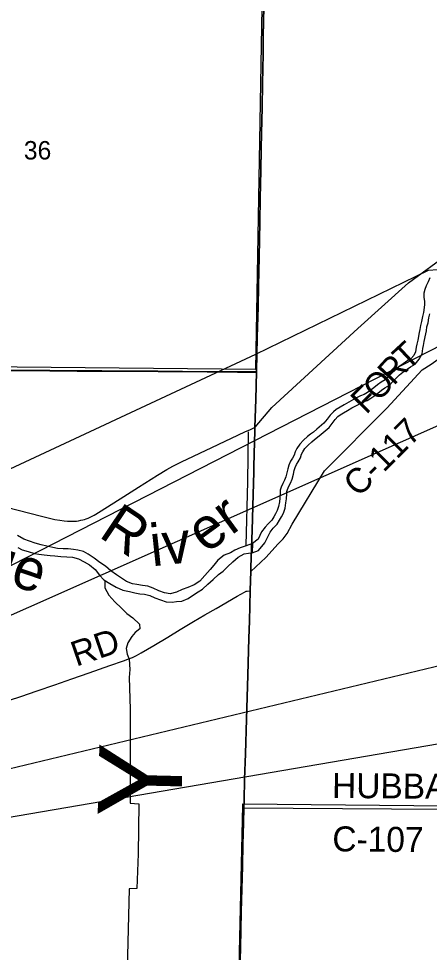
# Model space of a CAD drawing. Extents: x -8.3 to 42.1, y 0 to 22.
# Drawn here: x 7.372 to 8.304, y 16.982 to 19.103 of the extents above; entities that cross this region are included whole.
import ezdxf

# ---------------------------------------------------------------- set-up
doc = ezdxf.new("R2010")
doc.units = 0
for name, color, linetype in [('GM_X_County_Road', 7, 'Continuous'), ('GM_X_County_Road_Text', 7, 'Continuous'), ('GM_X_County_Text', 7, 'Continuous'), ('GM_X_Major_River', 7, 'Continuous'), ('GM_X_Major_River_Text', 7, 'Continuous'), ('GM_X_Minor_River', 7, 'Continuous'), ('GM_X_Rail_Line', 7, 'Continuous'), ('GM_X_Section', 7, 'Continuous'), ('GM_X_Section_Text', 7, 'Continuous'), ('GM_X_State_Route', 7, 'Continuous'), ('GM_X_Township_Road', 7, 'Continuous'), ('GM_X_Township_Road_Text', 7, 'Continuous'), ('GM_X_US_Route', 7, 'Continuous'), ('SH_Cut_Line', 7, 'Continuous'), ('SH_Text', 7, 'Continuous')]:
    doc.layers.add(name, color=color, linetype=linetype)

msp = doc.modelspace()

# ---------------------------------------------------------------- linework, layer by layer
at = {"layer": 'GM_X_County_Road'}
for points in [[(7.8987, 17.8473), (7.933, 17.8784), (7.9603, 17.9099), (7.9717, 17.9213), (7.9812, 17.9331), (7.9926, 17.9548), (8.0656, 18.0756), (8.2076, 18.2177), (8.2873, 18.3051), (8.3078, 18.3181), (8.5197, 18.4682), (8.7205, 18.6119), (8.7539, 18.6347), (8.8458, 18.7042), (8.9, 18.7436)], [(6.9106, 18.3053), (6.945, 18.3048), (6.9948, 18.3048), (7.029, 18.3045), (7.0663, 18.3044), (7.0911, 18.3043), (7.144, 18.3041), (7.2186, 18.3036), (7.2559, 18.3034), (7.3398, 18.3031), (7.4424, 18.3029), (7.5045, 18.3023), (7.5605, 18.3019), (7.6413, 18.3016), (7.6879, 18.3013), (7.7998, 18.3003), (7.8682, 18.3), (7.9024, 18.2999), (7.9119, 18.2999)], [(7.8831, 17.31), (8.8875, 17.3037), (8.9, 17.3036)]]:
    msp.add_lwpolyline(points, dxfattribs=at)
at = {"layer": 'GM_X_Major_River'}
msp.add_line((7.9027, 17.9106), (7.9019, 17.889), dxfattribs=at)
for points in [[(8.3052, 18.5138), (8.3014, 18.5047), (8.2969, 18.4956), (8.2935, 18.4872), (8.2913, 18.4792), (8.2913, 18.4697), (8.2925, 18.4599), (8.2925, 18.4534), (8.2921, 18.4466), (8.2903, 18.4352), (8.2881, 18.426), (8.2862, 18.415), (8.2836, 18.4059), (8.2821, 18.3964), (8.2806, 18.3899), (8.2773, 18.3721), (8.2754, 18.3633), (8.2739, 18.3565), (8.2724, 18.3462), (8.2683, 18.3379), (8.2615, 18.3299), (8.2524, 18.3249), (8.2441, 18.3188), (8.2342, 18.3115), (8.2259, 18.3046), (8.2176, 18.2966), (8.21, 18.289), (8.2036, 18.2821), (8.1945, 18.2767), (8.1862, 18.2706), (8.1779, 18.2641), (8.1714, 18.2592), (8.1631, 18.2538), (8.1555, 18.2492), (8.1476, 18.2458), (8.1411, 18.2427), (8.1317, 18.2377), (8.1207, 18.2319), (8.1101, 18.2258), (8.1014, 18.2205), (8.0923, 18.2151), (8.0859, 18.2097), (8.0787, 18.2021), (8.0715, 18.1926), (8.0643, 18.1838)], [(8.0761, 18.1742), (8.0834, 18.1832), (8.0903, 18.1923), (8.0963, 18.1987), (8.1011, 18.2027), (8.1092, 18.2075), (8.1179, 18.2128), (8.128, 18.2187), (8.1387, 18.2243), (8.1479, 18.2291), (8.1539, 18.232), (8.1625, 18.2357), (8.1711, 18.2409), (8.1802, 18.2468), (8.1872, 18.2522), (8.1953, 18.2585), (8.2029, 18.2641), (8.2132, 18.2702), (8.221, 18.2785), (8.2282, 18.2858), (8.236, 18.2933), (8.2436, 18.2995), (8.2531, 18.3066), (8.2606, 18.3121), (8.2712, 18.3179), (8.281, 18.3295), (8.2871, 18.3417), (8.2888, 18.3538), (8.2902, 18.3601), (8.2921, 18.3691), (8.2954, 18.3868), (8.297, 18.3935), (8.2984, 18.4026), (8.301, 18.4117), (8.3029, 18.423), (8.3052, 18.4321)], [(7.9019, 17.889), (7.9163, 17.8944), (7.9303, 17.9124), (7.9428, 17.9361), (7.9493, 17.9451), (7.958, 17.9544), (7.964, 17.9636), (7.9681, 17.9711), (7.9725, 17.9796), (7.9762, 17.9909), (7.9783, 18.0029), (7.9795, 18.0117), (7.9803, 18.0234), (7.9803, 18.0288), (7.9819, 18.0332), (7.9849, 18.0407), (7.9886, 18.0477), (7.9927, 18.057), (7.9953, 18.0681), (7.997, 18.0765), (7.9993, 18.083), (8.002, 18.0903), (8.0057, 18.096), (8.0111, 18.1048), (8.0135, 18.1132), (8.0163, 18.119), (8.0213, 18.1264), (8.0288, 18.1341), (8.0367, 18.1417), (8.0432, 18.1465), (8.0501, 18.1518), (8.0583, 18.1589), (8.0761, 18.1742)], [(8.0643, 18.1838), (8.0485, 18.1704), (8.0405, 18.1636), (8.0341, 18.1586), (8.0269, 18.1533), (8.0182, 18.1449), (8.0095, 18.1361), (8.0031, 18.1266), (7.9993, 18.1186), (7.9971, 18.111), (7.9929, 18.1041), (7.9884, 18.0972), (7.985, 18.0881), (7.9824, 18.0805), (7.9805, 18.0714), (7.9783, 18.0619), (7.9749, 18.0543), (7.9711, 18.047), (7.9678, 18.0387), (7.9651, 18.0315), (7.9652, 18.0239), (7.9644, 18.0132), (7.9633, 18.0052), (7.9615, 17.9946), (7.9585, 17.9855), (7.9547, 17.9783), (7.9509, 17.9714), (7.946, 17.9638), (7.9381, 17.9554), (7.9309, 17.9474), (7.9227, 17.9368), (7.915, 17.9204), (7.9027, 17.9106)], [(7.9027, 17.9106), (7.8878, 17.9054), (7.8744, 17.9008), (7.8625, 17.8954), (7.8522, 17.8896), (7.838, 17.8838), (7.8239, 17.8724), (7.8144, 17.8613), (7.8065, 17.8512), (7.7945, 17.8382), (7.7832, 17.8252), (7.7697, 17.8168), (7.7555, 17.8103), (7.7426, 17.8061), (7.7295, 17.8003), (7.7158, 17.7965), (7.703, 17.7983), (7.6895, 17.8032), (7.6771, 17.8092), (7.6647, 17.8133), (7.6527, 17.8155), (7.6398, 17.8173), (7.63, 17.8187), (7.6161, 17.8243), (7.605, 17.8322), (7.5938, 17.8397), (7.5811, 17.8483), (7.5685, 17.8589), (7.5559, 17.8675), (7.5432, 17.8769), (7.5294, 17.8864), (7.519, 17.8923), (7.5062, 17.8953), (7.496, 17.8971), (7.4839, 17.8981), (7.4726, 17.8988), (7.4597, 17.8991), (7.4492, 17.9016), (7.4356, 17.9042), (7.4224, 17.9076), (7.4093, 17.9113), (7.3961, 17.9158), (7.3833, 17.9203), (7.3692, 17.929)], [(7.3696, 17.9017), (7.3797, 17.8965), (7.3929, 17.8924), (7.4075, 17.8878), (7.4173, 17.8865), (7.4294, 17.885), (7.4434, 17.8835), (7.4536, 17.8822), (7.4672, 17.8811), (7.4808, 17.8804), (7.494, 17.8793), (7.5076, 17.8755), (7.5203, 17.8688), (7.5322, 17.862), (7.5452, 17.8515), (7.5548, 17.8387), (7.5646, 17.8283), (7.5782, 17.8199), (7.5927, 17.8112), (7.6081, 17.8044), (7.6231, 17.8014), (7.6356, 17.7984), (7.6465, 17.7966), (7.6575, 17.7956), (7.6695, 17.7923), (7.6804, 17.7871), (7.7062, 17.7777), (7.7199, 17.7774), (7.7298, 17.7791), (7.7423, 17.7799), (7.756, 17.7853), (7.7661, 17.7926)], [(7.7661, 17.7926), (7.7792, 17.801), (7.7888, 17.8072), (7.8008, 17.8179), (7.8132, 17.829), (7.8252, 17.8401), (7.8356, 17.8478), (7.8457, 17.8575), (7.8581, 17.8689), (7.8701, 17.8793), (7.8832, 17.8869), (7.893, 17.8886), (7.9019, 17.889)]]:
    msp.add_lwpolyline(points, dxfattribs=at)
at = {"layer": 'GM_X_Minor_River'}
for points in [[(7.8882, 17.9058), (7.8914, 18.051), (7.8931, 18.1641)], [(7.5669, 17.8244), (7.5669, 17.81), (7.5764, 17.7934), (7.59, 17.7779), (7.6052, 17.7639), (7.617, 17.7514), (7.6311, 17.7416), (7.6459, 17.7272), (7.6468, 17.7166), (7.6364, 17.7088), (7.6282, 17.6995), (7.6191, 17.685), (7.6158, 17.6721), (7.6181, 17.6592), (7.6224, 17.6477), (7.624, 17.6241), (7.6221, 17.6063), (7.6245, 17.5342), (7.6245, 17.3979), (7.6248, 17.3205), (7.6445, 17.3196), (7.6428, 17.2054), (7.6401, 17.1269), (7.6223, 17.1266), (7.6193, 17.0045), (7.6167, 16.8842)]]:
    msp.add_lwpolyline(points, dxfattribs=at)
at = {"layer": 'GM_X_Rail_Line'}
for points in [[(7.9103, 18.3409), (8.3022, 18.5316), (8.3223, 18.533), (8.5169, 18.6965), (8.5964, 18.7584), (8.9, 19.0594)], [(5.9044, 17.3082), (6.0693, 17.3942), (6.218, 17.4628), (6.6389, 17.7213), (6.9437, 17.9671), (7.085, 17.9703), (7.2495, 18.0325), (7.9103, 18.3409)]]:
    msp.add_lwpolyline(points, dxfattribs=at)
at = {"layer": 'GM_X_Section'}
for points in [[(7.9268, 19.313), (7.9258, 19.2592), (7.9095, 18.3054), (6.9034, 18.3155), (6.9241, 19.3275)], [(7.8808, 17.3192), (8.8895, 17.3091), (8.8613, 16.3047), (7.8576, 16.3068), (7.8577, 16.3121), (7.8807, 17.3166)]]:
    msp.add_lwpolyline(points, close=True, dxfattribs=at)
at = {"layer": 'GM_X_State_Route'}
for points in [[(7.9083, 18.1745), (7.9462, 18.2196), (8.1416, 18.3992), (8.2566, 18.5029), (8.4426, 18.6386), (8.5067, 18.6856), (8.6077, 18.7682), (8.7266, 18.8854), (8.8749, 19.0334), (8.9, 19.058)], [(7.3437, 17.9933), (7.4238, 17.9728), (7.4449, 17.9674), (7.454, 17.9653), (7.465, 17.9632), (7.475, 17.9618), (7.4824, 17.9612), (7.49, 17.961), (7.4975, 17.9612), (7.5026, 17.9616), (7.5078, 17.9623), (7.5124, 17.9632), (7.5171, 17.9642), (7.5211, 17.9654), (7.5252, 17.9668), (7.5291, 17.9683), (7.5323, 17.9698), (7.5351, 17.9711), (7.5383, 17.9727), (7.5428, 17.975), (7.547, 17.9774), (7.5527, 17.9807), (7.6023, 18.0117), (7.6437, 18.0385), (7.6869, 18.0657), (7.7082, 18.0786), (7.7216, 18.0863), (7.7307, 18.0911), (7.7411, 18.0961), (7.8101, 18.1289), (7.8851, 18.1638), (7.8978, 18.1697), (7.9083, 18.1745)]]:
    msp.add_lwpolyline(points, dxfattribs=at)
at = {"layer": 'GM_X_Township_Road'}
for points in [[(7.3396, 18.3036), (7.4421, 18.3034), (7.5043, 18.3029), (7.5602, 18.3025), (7.6411, 18.3021), (7.6877, 18.3019), (7.7996, 18.3008), (7.868, 18.3005), (7.9022, 18.3005), (7.9117, 18.3005), (7.9117, 18.3027), (7.9133, 18.3789), (7.9149, 18.4473), (7.9158, 18.4955), (7.9172, 18.5607), (7.9189, 18.6415), (7.9199, 18.6944), (7.9216, 18.7581), (7.9223, 18.8078), (7.923, 18.842), (7.924, 18.9011), (7.925, 18.9555), (7.9262, 19.0223), (7.9263, 19.0379), (7.9267, 19.0643), (7.9276, 19.0953), (7.928, 19.1295)], [(7.928, 19.1295), (7.9276, 19.0953), (7.9267, 19.0643), (7.9263, 19.0379), (7.9262, 19.0223), (7.925, 18.9555), (7.924, 18.9011), (7.923, 18.842), (7.9223, 18.8078), (7.9216, 18.7581), (7.9199, 18.6944), (7.9189, 18.6415), (7.9172, 18.5607), (7.9158, 18.4955), (7.9149, 18.4473), (7.9133, 18.3789), (7.9117, 18.3027), (7.9117, 18.3005), (7.91, 18.2375), (7.908, 18.1751), (7.9078, 18.166), (7.9062, 18.1147), (7.9062, 18.1101), (7.9056, 18.0883), (7.9053, 18.0728), (7.9036, 18.0215), (7.9013, 17.9407), (7.8988, 17.8568), (7.8985, 17.8479), (7.8971, 17.804), (7.8971, 17.8036), (7.8952, 17.7341), (7.8942, 17.6952), (7.8916, 17.6113), (7.8886, 17.5119), (7.8863, 17.4327), (7.8845, 17.3752), (7.8833, 17.327), (7.8829, 17.3106), (7.882, 17.2757), (7.8808, 17.2276), (7.8795, 17.1778), (7.8768, 17.0738), (7.8758, 17.0333), (7.8748, 16.993), (7.8741, 16.965)], [(7.8741, 16.965), (7.8748, 16.993), (7.8758, 17.0333), (7.8768, 17.0738), (7.8795, 17.1778), (7.8808, 17.2276), (7.882, 17.2757), (7.8829, 17.3106), (7.8833, 17.327), (7.8845, 17.3752), (7.8863, 17.4327), (7.8886, 17.5119), (7.8916, 17.6113), (7.8942, 17.6952), (7.8952, 17.7341), (7.8971, 17.8036), (7.8971, 17.804), (7.8985, 17.8479), (7.8988, 17.8568), (7.9013, 17.9407), (7.9036, 18.0215), (7.9053, 18.0728), (7.9056, 18.0883), (7.9062, 18.1101), (7.9062, 18.1147), (7.9078, 18.166), (7.908, 18.1751), (7.91, 18.2375), (7.9117, 18.3005), (7.9022, 18.3005), (7.868, 18.3005), (7.7996, 18.3008), (7.6877, 18.3019), (7.6411, 18.3021), (7.5602, 18.3025), (7.5043, 18.3029), (7.4421, 18.3034), (7.3396, 18.3036)], [(7.3509, 17.5544), (7.3768, 17.5632), (7.4138, 17.5759), (7.4538, 17.5898), (7.492, 17.603), (7.5319, 17.6169), (7.5789, 17.6332), (7.6095, 17.6438), (7.6194, 17.6475), (7.6298, 17.6519), (7.6388, 17.6562), (7.6497, 17.662), (7.6782, 17.6787), (7.7101, 17.6982), (7.7383, 17.7153), (7.7686, 17.7336), (7.7938, 17.7483), (7.8196, 17.7633), (7.8675, 17.7911), (7.8841, 17.8004), (7.8857, 17.8011), (7.8868, 17.8016), (7.8881, 17.802), (7.8892, 17.8022), (7.8906, 17.8024), (7.8973, 17.8031)]]:
    msp.add_lwpolyline(points, dxfattribs=at)
at = {"layer": 'GM_X_US_Route'}
for points in [[(7.9119, 18.2999), (7.912, 18.3022), (7.9135, 18.3783), (7.9151, 18.4467), (7.916, 18.4949), (7.9174, 18.5602), (7.9191, 18.641), (7.9201, 18.6938), (7.9218, 18.7575), (7.9226, 18.8073), (7.9232, 18.8415), (7.9242, 18.9005), (7.9252, 18.9549), (7.9264, 19.0218), (7.9265, 19.0373), (7.927, 19.0637), (7.9278, 19.0948), (7.9282, 19.129)], [(7.8743, 16.9644), (7.875, 16.9924), (7.876, 17.0328), (7.877, 17.0732), (7.8797, 17.1773), (7.881, 17.227), (7.8822, 17.2752), (7.8831, 17.31), (7.8835, 17.3265), (7.8847, 17.3746), (7.8865, 17.4321), (7.8888, 17.5113), (7.8918, 17.6108), (7.8944, 17.6947), (7.8954, 17.7335), (7.8973, 17.8031), (7.8987, 17.8473), (7.899, 17.8562), (7.9015, 17.9401), (7.9039, 18.0209), (7.9056, 18.0722), (7.9058, 18.0878), (7.9064, 18.1095), (7.9064, 18.1142), (7.908, 18.1654), (7.9083, 18.1745), (7.9102, 18.2369), (7.9119, 18.2999)]]:
    msp.add_lwpolyline(points, dxfattribs=at)
at = {"layer": 'SH_Cut_Line'}
for points in [[(7.8741, 16.965), (7.8748, 16.993), (7.8758, 17.0333), (7.8768, 17.0738), (7.8795, 17.1778), (7.8808, 17.2276), (7.882, 17.2757), (7.8829, 17.3106), (7.8833, 17.327), (7.8845, 17.3752), (7.8863, 17.4327), (7.8886, 17.5119), (7.8916, 17.6113), (7.8942, 17.6952), (7.8952, 17.7341), (7.8971, 17.8036), (7.8971, 17.804), (7.8985, 17.8479), (7.8988, 17.8568), (7.9013, 17.9407), (7.9036, 18.0215), (7.9053, 18.0728), (7.9056, 18.0883), (7.9062, 18.1101), (7.9062, 18.1147), (7.9078, 18.166), (7.908, 18.1751), (7.91, 18.2375), (7.9117, 18.3005), (7.9117, 18.3027), (7.9133, 18.3789), (7.9149, 18.4473), (7.9158, 18.4955), (7.9172, 18.5607), (7.9189, 18.6415), (7.9199, 18.6944), (7.9216, 18.7581), (7.9223, 18.8078), (7.923, 18.842), (7.924, 18.9011), (7.925, 18.9555), (7.9262, 19.0223), (7.9263, 19.0379), (7.9267, 19.0643), (7.9276, 19.0953), (7.928, 19.1295)], [(7.928, 19.1295), (7.9276, 19.0953), (7.9267, 19.0643), (7.9263, 19.0379), (7.9262, 19.0223), (7.925, 18.9555), (7.924, 18.9011), (7.923, 18.842), (7.9223, 18.8078), (7.9216, 18.7581), (7.9199, 18.6944), (7.9189, 18.6415), (7.9172, 18.5607), (7.9158, 18.4955), (7.9149, 18.4473), (7.9133, 18.3789), (7.9117, 18.3027), (7.9117, 18.3005), (7.91, 18.2375), (7.908, 18.1751), (7.9078, 18.166), (7.9062, 18.1147), (7.9062, 18.1101), (7.9056, 18.0883), (7.9053, 18.0728), (7.9036, 18.0215), (7.9013, 17.9407), (7.8988, 17.8568), (7.8985, 17.8479), (7.8971, 17.804), (7.8971, 17.8036), (7.8952, 17.7341), (7.8942, 17.6952), (7.8916, 17.6113), (7.8886, 17.5119), (7.8863, 17.4327), (7.8845, 17.3752), (7.8833, 17.327), (7.8829, 17.3106), (7.882, 17.2757), (7.8808, 17.2276), (7.8795, 17.1778), (7.8768, 17.0738), (7.8758, 17.0333), (7.8748, 16.993), (7.8741, 16.965)]]:
    msp.add_lwpolyline(points, dxfattribs=at)
at = {"layer": 'SH_Text'}
for points in [[(9.5811, 19.002), (5.7134, 17.0195), (9.5811, 18.737)], [(9.5811, 17.9343), (5.7594, 17.0162), (9.5811, 17.6715)]]:
    msp.add_lwpolyline(points, close=True, dxfattribs=at)

# ---------------------------------------------------------------- texts
at = {"layer": 'GM_X_County_Road_Text'}
for s, height, rotation, p in [('T', 0.0568, 42.8964, (8.2535, 18.301)), ('R', 0.0568, 47.45, (8.2228, 18.2674)), ('O', 0.0568, 47.0338, (8.1884, 18.2305)), ('F', 0.0568, 45.3662, (8.1603, 18.2019)), ('C-117', 0.05682, 45, (8.1433, 18.0138)), ('HUBBARD', 0.05682, 359.5779, (8.0828, 17.3326)), ('C-107', 0.05682, 359.4494, (8.0834, 17.2115))]:
    msp.add_text(s, height=height, rotation=rotation, dxfattribs=at).set_placement(p)
at = {"layer": 'GM_X_County_Text'}
msp.add_text('Y', height=0.1894, rotation=88.6072, dxfattribs=at).set_placement((7.7402, 17.2862))
at = {"layer": 'GM_X_Major_River_Text'}
for s, height, rotation, p in [('er', 0.09475, 36.2255, (7.7969, 17.8862)), ('R', 0.0948, 326.2233, (7.5508, 17.9272)), ('iv', 0.09475, 6.2243, (7.6744, 17.8585)), ('ge', 0.09475, 341.2231, (7.2823, 17.8407))]:
    msp.add_text(s, height=height, rotation=rotation, dxfattribs=at).set_placement(p)
at = {"layer": 'GM_X_Section_Text'}
msp.add_text('36', height=0.04186, rotation=0, dxfattribs=at).set_placement((7.3834, 18.7827))
at = {"layer": 'GM_X_Township_Road_Text'}
msp.add_text('RD', height=0.05682, rotation=18.8993, dxfattribs=at).set_placement((7.5023, 17.6305))

doc.saveas('drawing.dxf')
